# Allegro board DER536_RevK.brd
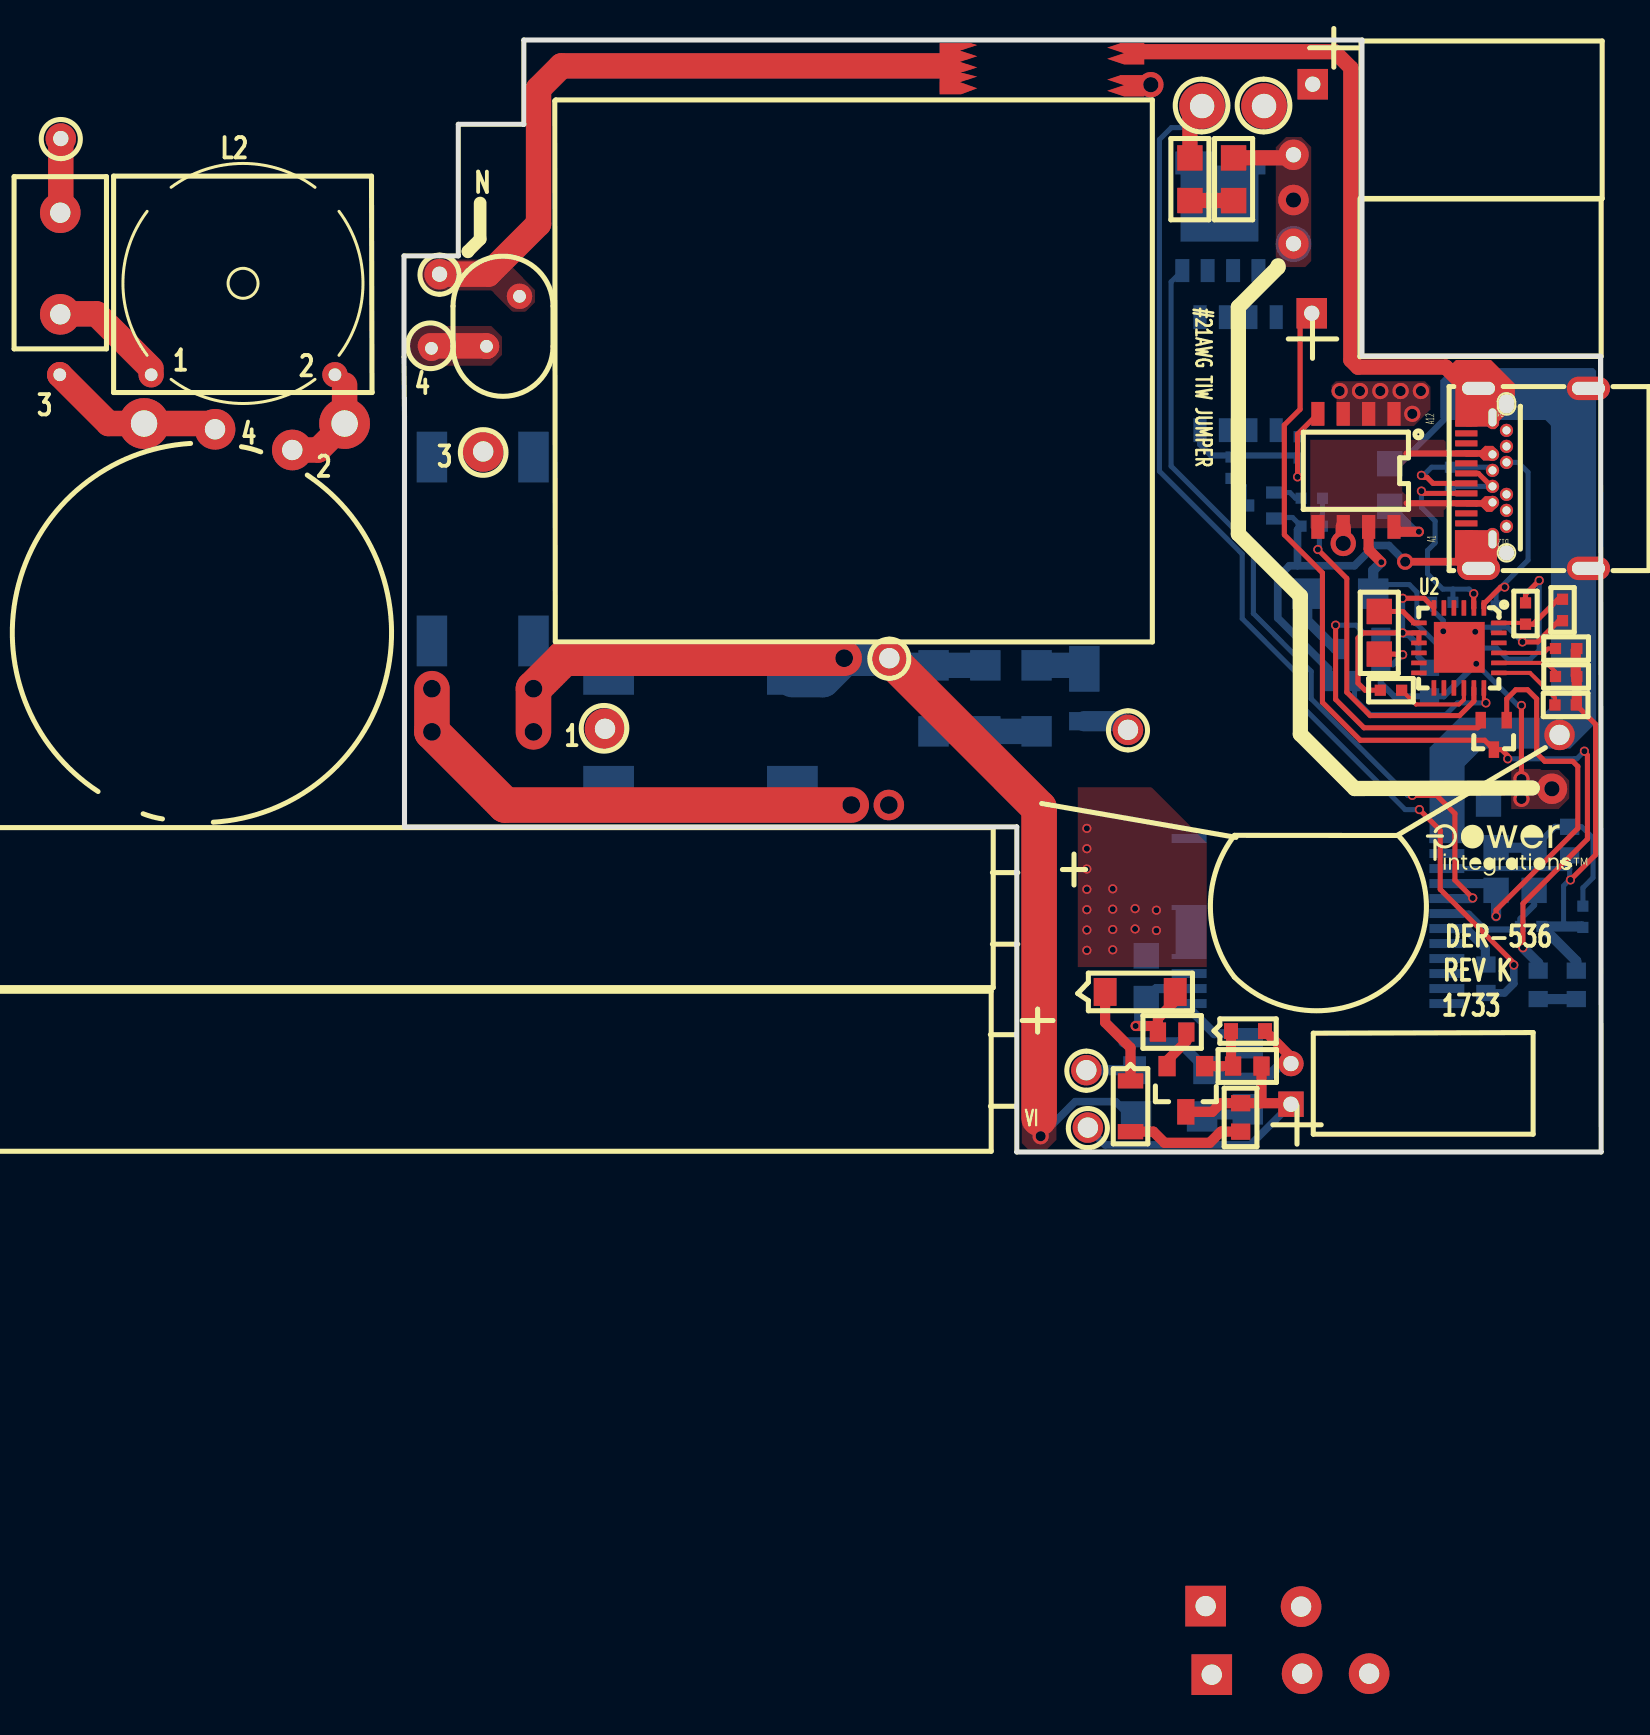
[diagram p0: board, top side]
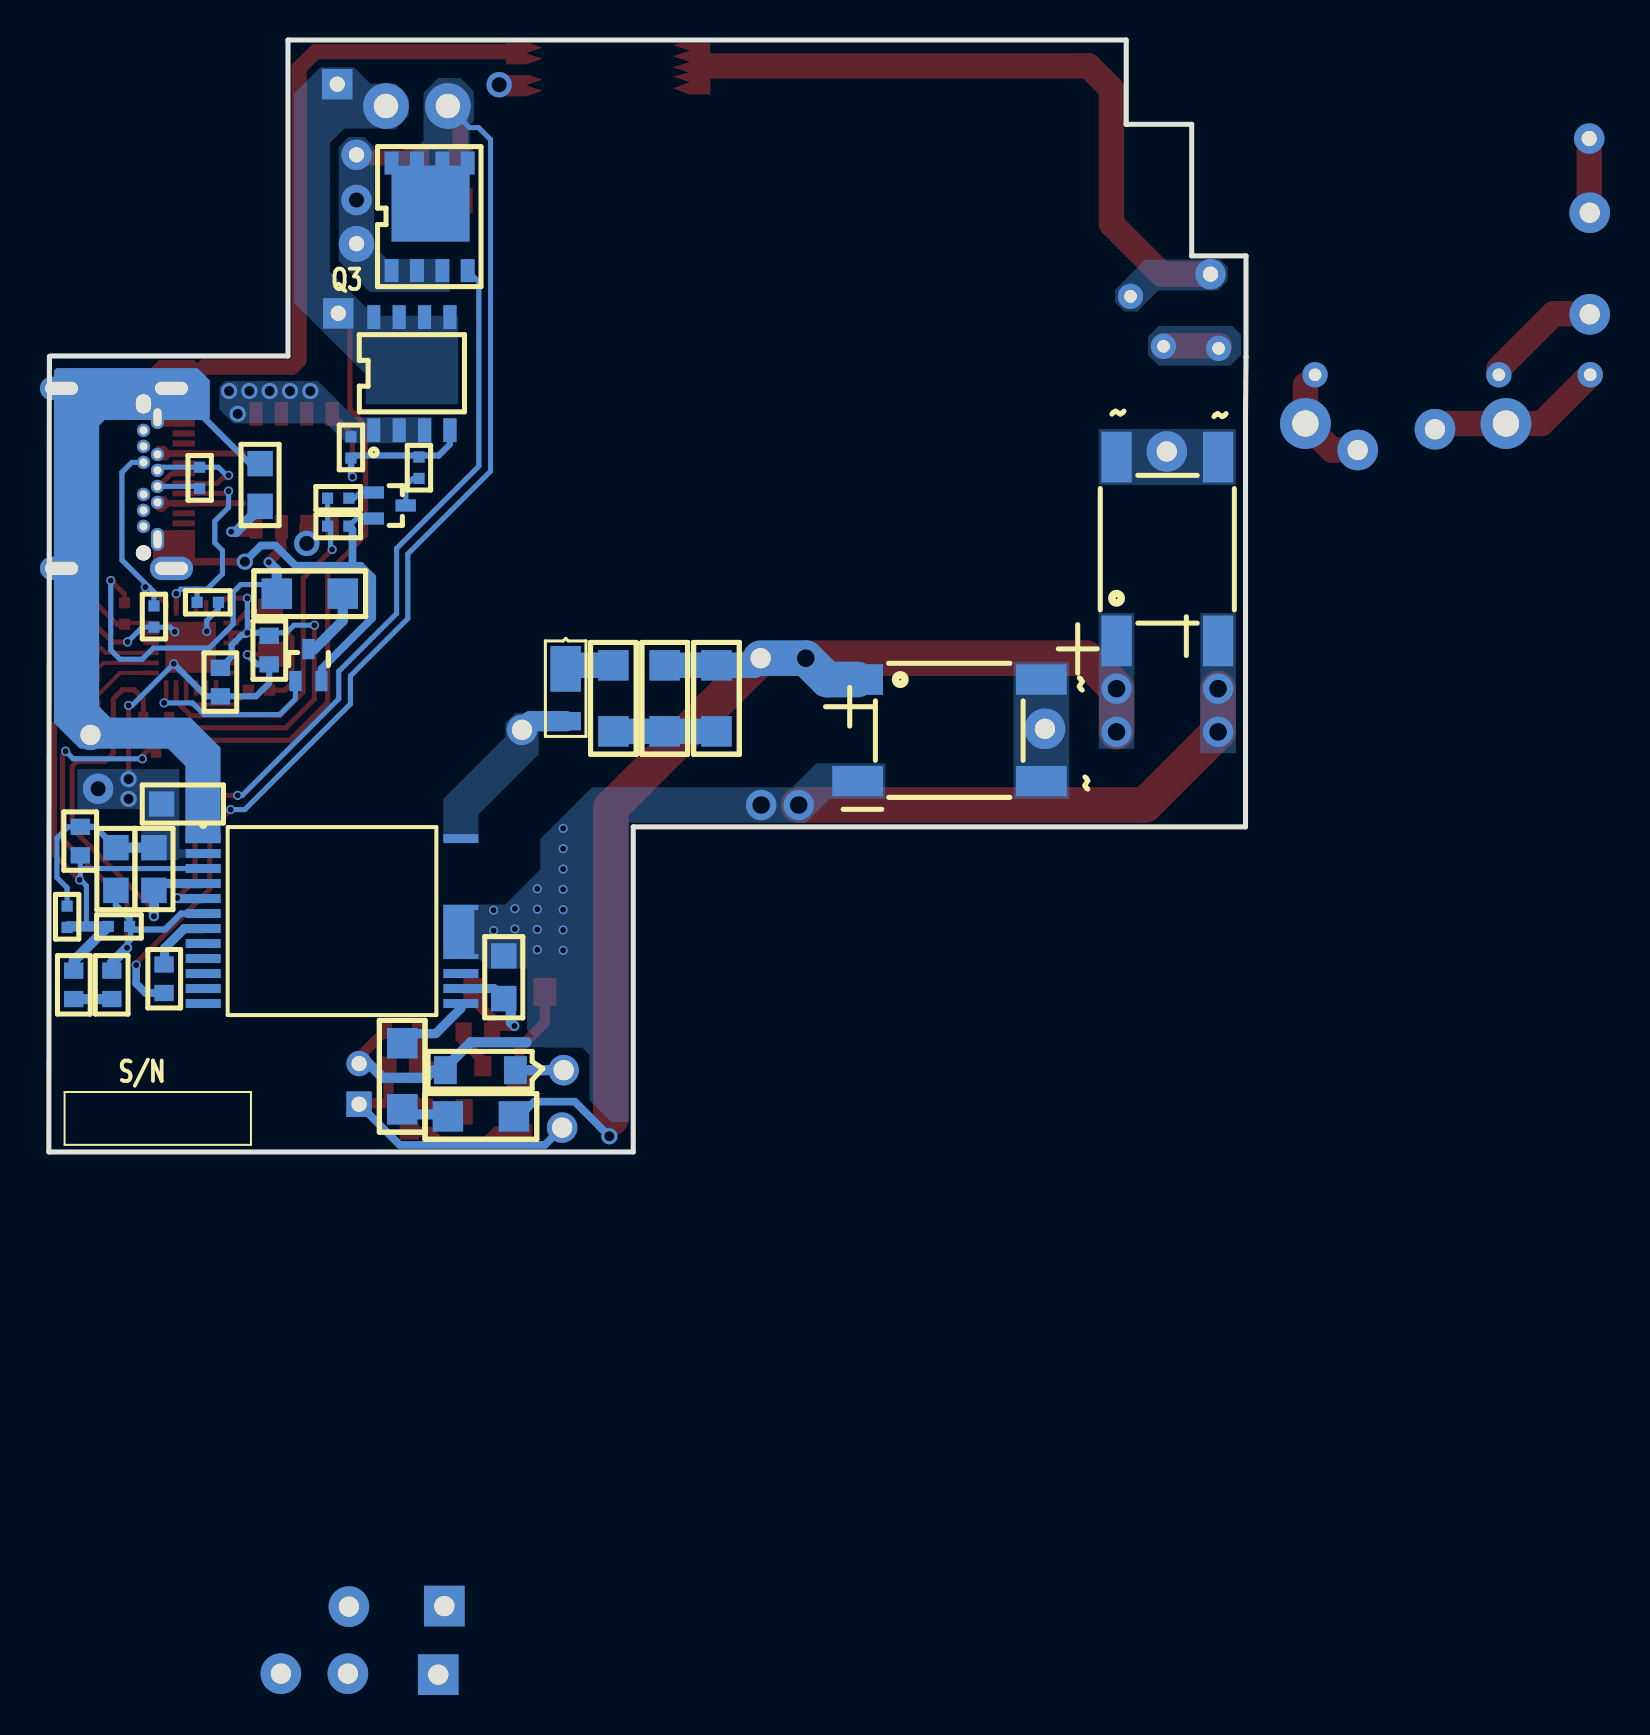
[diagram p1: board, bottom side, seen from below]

Outline 59.89 x 55.6 mm; copper layers: TOP, BOTTOM. Coordinates in mm from the lower left corner of the outline.
Outline path: 59.82,39.8 47.93,39.8 47.93,55.6 5.99,55.6 5.99,51.38 2.72,51.38 2.72,44.81 0,44.81 0,39.75 0.03,36.78 0.03,16.26 30.66,16.26 30.66,0 59.89,0 59.87,39.78

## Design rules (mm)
constraint set DEFAULT: min track width 0.508

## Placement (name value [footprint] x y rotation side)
BR1  TBS20J-TP  [PISMD_4-TBS]  6.48 25.6 0 bottom
BR2  TBS20J-TP  [PISMD_4-TBS]  19.38 23.62 90 bottom
C1  1 nF  [PINPYCAPRAD540X290LS400040H]  50.6 19.84 180 top
C2  39 uF  [PI_POLCAP315LS138D063]  31.98 13.97 270 top
C3  39 uF  [PI_POLCAP315LS138D063#2]  31.88 2.29 90 bottom
C4  2.2 nF  [PISMC1206]  29.08 24.33 270 bottom
C5  6.8 nF  [PISMC0603]  56.74 9.07 270 bottom
C6  390 uF  [PIPOLCAPCLYD320LS140030#2]  45.42 43.71 90 bottom
C7  390 uF  [PIPOLCAPCLYD320LS140030]  45.47 51.61 270 top
C8  1 nF  [PISMC0805]  41.5 47.57 90 top
C9  10 uF  [PISMC0805]  49.33 32.28 90 bottom
C10  2.2 uF  [PISMC0805]  54.64 15.21 270 bottom
C11  330 pF  [PISMC0603]  58.32 16.26 270 bottom
C12  100 nF  [PI_NP_XCAP_RAD512X197X395D040_H]  -2.97 36.42 180 top
C13  2.2 uF  [PISMC0805]  56.54 15.21 270 bottom
C14  22 uF  [PIPOLCAPCLYD200LS80030H]  44.37 2.39 90 top
C15  4.7 uF  [PISMC0805]  37.13 7.67 90 bottom
C16  100 nF  [PISMC0603]  51.31 24.21 270 bottom
C17  1 uF  [PISMC0603]  48.87 24.38 90 bottom
C18  1 uF  [PISMC0805]  48.79 24.89 90 top
C19  330 pF  [PISMR0402]  52.48 27.48 180 bottom
C20  330 pF  [PISMR0402]  54.64 27.3 270 bottom
D1  DFLR1800-7  [PISMDDFLR120012]  34.04 24.18 90 bottom
D2  BAV21WS-7-F  [PISMSOD323]  36.35 3.56 270 top
D3  SM4003PL-TP  [PI_SM_SOD-123_12]  36.55 4.09 0 bottom
F1  2 A  [PI_RST_MICROFUSE]  -17.2 46.96 270 top
FL1  Hole_30mils  [PI_HOLE_30MIL]  24.28 24.69 0 top
FL2  Hole_50mils  [PI_HOLE_50MIL]  39.93 52.3 0 top
FL3  Hole_50mils  [PI_HOLE_50MIL]  43.03 52.3 0 top
FL4  Hole_30mils  [PI_HOLE_30MIL]  36.22 21.11 0 top
FL5  Hole_30mils  [PI_HOLE_30MIL]  34.21 1.22 0 top
FL6  Hole_30mils  [PI_HOLE_30MIL]  34.14 4.09 0 top
J1  PCB Terminal 30 AWG  [PI_HOLE_30AWG]  -17.17 50.67 0 top
J2  PCB Terminal 30 AWG  [PI_HOLE_30AWG]  1.78 43.89 0 top
J3  USB-C/3.1  [PI_CONN_USB_3P1_TOP]  54.46 33.68 90 top
L1  34 mH  [PI_CMCHOKE_19X10MMH]  -10.77 15.78 165 top
L2  600 uH  [PI_TOROID_CMC4P_H]  -8.05 43.43 180 top
NOREF  -  []  0 44.81 0 top
NOREF#2  -  []  59.89 0 90 top
NOREF#3  -  []  -20.62 0.04 0 top
NOREF#4  -  []  50.57 16.28 0 top
NOREF#5  -  []  -174.86 61.37 0 top
NOREF#6  -  []  -252.68 -137.64 0 top
Q1  BSC030P03NS3 G  [PI_SM_PG-TDSON-8]  43.64 36.09 180 bottom
Q2  BSC030P03NS3 G  [PI_SM_PG-TDSON-8]  49.53 36.91 180 top
Q3  SIR882ADP-T1-GE3  [PI_SM_POWERPAK_SO-8_SINGLE]  42.75 44.07 180 bottom
Q4  RJU003N03T106  [PISMSOT323]  43.64 31.67 270 bottom
Q5  RJU003N03T106  [PISMSOT323]  46.25 23.55 180 bottom
Q6  RU1J002YNTCL  [PI_SM_UMT3F]  55.17 21.59 180 top
Q7  MMBTA06LT1G  [PISMSOT23123_1]  38.18 4.29 180 top
R1  2.00 M  [PISMR1206]  39.93 1.78 180 bottom
R2  150 k  [PISMR1206]  26.49 24.33 270 bottom
R3  1.80 M  [PISMR1206]  42.21 5.44 270 bottom
R4  100.0 k  [PISMR0402]  55.85 11.28 0 bottom
R5  20  [PISMR1206]  31.65 21.03 90 bottom
R6  49.9 k  [PISMR0402]  44.78 35.76 270 bottom
R7  200  [PISMR1206]  48.49 27.91 180 bottom
R8  10  [PISMR0805]  39.32 47.57 90 top
R9  1.00 k  [PISMR0402]  41.38 34.75 270 bottom
R10  4.02 k  [PISMR0603]  58.65 7.65 90 bottom
R11  10  [PISMR0402]  45.95 32.69 180 bottom
R12  100.0 k  [PISMR0402]  45.95 31.29 180 bottom
R13  47  [PISMR0603]  54.13 7.95 90 bottom
R14  402  [PISMR0603]  41.86 2.44 270 top
R15  1.50 M  [PISMR0603]  42.9 4.29 180 top
R16  31.6 k  [PISMR0402]  58.98 12.29 270 bottom
R17  31.6 k  [PISMR0402]  58.65 22.35 180 top
R18  18.0 k  [PISMR0402]  58.67 23.77 180 top
R19  12.7 k  [PISMR0402]  58.67 25.17 180 top
R20  4.02 k  [PISMR0603]  39.14 5.99 180 top
R21  0.01  [PISMR0805]  54.25 17.4 180 bottom
R22  100  [PISMR0402]  52.35 33.17 90 bottom
R23  100.0 k  [PISMR0402]  56.11 27.46 270 top
R24  10.0 k  [PISMR0402]  57.96 27.64 270 top
R25  4.7 k  [PISMR0402]  49.91 23.09 180 top
RT1  5  [PI_RAD_276DX197T_LS100D025]  4.95 40.28 90 top
U1  INN3268C  [PI_IC_INSOP_24D]  52.17 15.67 180 bottom
U2  CYPD2134-24LQXIT  [PI_SM_24_QFN]  54.03 27.2 180 top
VR1  MMSZ5259BT1G  [PI_SM_SOD-123_12]  35.08 8 0 top
VR2  DZ2S100M0L  [PI_SM_D_SSMINI2P]  41.38 6.05 0 top

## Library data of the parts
BR1 BR2 = DIODE BRIDGE_+-~~
C1 = CAP NP: alternate symbols: (pinpycaprad540x290ls400040h,pinpycaprad500x220ls400040)
C2 C3 = CAP POL: alternate symbols: (PI_POLCAP315LS138D063L2000H)
C4 C5 C8-C11 C13 C15-C20 = CAP NP
C6 C7 = CAP POL: alternate symbols: (pipolcapclyd320ls140d30h470)
C12 = CAP NP: alternate symbols: (pi_np_xcap_rad512x197x395d040_h)
C14 = CAP POL: alternate symbols: (pipolcapclyd200ls80030h)
D1-D3 = DIODE
F1 = FUSE: alternate symbols: (pirstmicrofusehoz)
FL1-FL6 = FlyingLead
J1 J2 = TERM_1Pin
J3 = CON24_USB: alternate symbols: (pi_conn_usb_3p1_topD)
L1 = TORRID 4P_12_34: alternate symbols: (pi_CMChoke_19x10mmH)
L2 = TORRID 4P_12_34: alternate symbols: (pi_toroid_CMC4p_V)
Q1 = FET_P_TDSON-8_15
Q2 = FET_P_TDSON-8_16
Q3 = FET_N_SGD_123_4_5678
Q4 Q5 = FET_N_SGD
Q6 = FET_N_GSD
Q7 = NPN_BEC
R1-R25 = R
RT1 = THERMISTOR
U1 = DEV_Inno3CP
U2 = CYPD2134-24LQXIT
VR1 VR2 = DIODE_ZENER

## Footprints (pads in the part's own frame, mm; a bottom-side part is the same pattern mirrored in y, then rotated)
PI_CMCHOKE_19X10MMH
  round 2.032 hole 1.016: 1(-18.723,-10.583) 2(0,-20) 3(-9.245,-22.401) 4(4,-20)
PI_CONN_USB_3P1_TOP
  oval 1.168x2.159 hole 0.66x1.651: (-4.5,0.7) (-4.5,-4.8) (4.5,0.7) (4.5,-4.8)
  round 0.762 hole 0.762: (-3.725,-0.7)
  oval 0.965x0.762 hole 0.965x0.762 unplated: (3.725,-0.7)
  rect 0.305x1.118 smd: A1(-2.75,1.31) A2(-2.25,1.31) A3(-1.75,1.31) A4(-1.25,1.31) A5(-0.75,1.31) A6(-0.25,1.31) A7(0.25,1.31) A8(0.75,1.31) A9(1.25,1.31) A10(1.75,1.31) A11(2.25,1.31) A12(2.75,1.31)
  oval 1.15x0.66 hole 0.9x0.406: B1(3.05,0) B12(-3.05,0)
  round 0.66 hole 0.406: B2(2.4,-0.7) B3(1.6,-0.7) B4(1.2,0) B5(0.8,-0.7) B6(0.4,0) B7(-0.4,0) B8(-0.8,-0.7) B9(-1.2,0) B10(-1.6,-0.7) B11(-2.4,-0.7)
PI_HOLE_30AWG
  round 1.524 hole 0.762: 1(0,0)
PI_HOLE_30MIL
  round 1.524 hole 1.016: 1(0,0)
PI_HOLE_50MIL
  round 2.286 hole 1.219: 1(0,0)
PI_IC_INSOP_24D
  rect 1.75x0.45 smd: 1(0,0) 2(0,-0.75) 3(0,-1.5) 4(0,-2.25) 5(0,-3) 6(0,-3.75) 7(0,-4.5) 8(0,-5.25) 9(0,-6) 10(0,-6.75) 11(0,-7.5) 12(0,-8.25) 13(12.89,-8.25) 14(12.89,-7.5) 15(12.89,-6.75) 24(12.89,0)
  custom 0.438x0.438 smd: 16(12.89,-4.67)
PI_NP_XCAP_RAD512X197X395D040_H
  round 2.54 hole 1.321: 1(0,0) 2(10.033,0)
PI_POLCAP315LS138D063
  rect 2.032x2.032 hole 1.016: 1(36.678,8.128)
  round 2.032 hole 1.016: 2(40.056,12.954)
PI_POLCAP315LS138D063#2
  rect 2.032x2.032 hole 1.016: 1(-28.423,8.534)
  round 2.032 hole 1.016: 2(-25.019,13.005)
PI_RAD_276DX197T_LS100D025
  round 1.27 hole 0.635: 1(0,0.826) 2(2.499,-0.826)
PI_RST_MICROFUSE
  round 2.032 hole 1.016: 1(0,0) 2(5.08,0)
PI_SM_24_QFN
  rect 0.231x0.775 smd: 1(0,0) 2(0.5,0) 3(1,0) 4(1.5,0) 5(2,0) 6(2.5,0) 13(2.5,4) 14(2,4) 15(1.5,4) 16(1,4) 17(0.5,4) 18(0,4)
  rect 0.775x0.231 smd: 7(3.25,0.75) 8(3.25,1.25) 9(3.25,1.75) 10(3.25,2.25) 11(3.25,2.75) 12(3.25,3.25) 19(-0.75,3.25) 20(-0.75,2.75) 21(-0.75,2.25) 22(-0.75,1.75) 23(-0.75,1.25) 24(-0.75,0.75)
  rect 2.54x2.54 smd: 25(1.23,1.97)
PI_SM_D_SSMINI2P
  rect 0.699x0.8 smd: 1(0,0) 2(1.699,0)
PI_SM_PG-TDSON-8
  rect 0.66x1.194 smd: 1(0,0) 2(1.27,0) 3(2.54,0) 4(3.81,0) 5(3.81,5.65) 6(2.54,5.65) 7(1.27,5.65) 8(0,5.65)
PI_SM_POWERPAK_SO-8_SINGLE
  rect 0.7x1.15 smd: 1(0,0) 2(1.27,0) 3(2.54,0) 4(3.81,0) 5(3.81,5.383) 6(2.54,5.383) 7(1.27,5.383) 8(0,5.383)
PI_SM_SOD-123_12
  rect 1.143x1.397 smd: 1(0,0) 2(3.505,0)
PI_SM_UMT3F
  rect 0.521x0.831 smd: 1(0,0) 2(1.301,0) 3(0.64,1.471)
PI_TOROID_CMC4P_H
  round 1.27 hole 0.635: 1(4.597,4.572) 2(-4.597,4.572) 3(9.169,4.572) 4(-9.423,3.251)
PINPYCAPRAD540X290LS400040H
  round 2.032 hole 1.016: 1(2.275,45.925)
  round 1.524 hole 1.016: 2(-7.213,-1.022)
PIPOLCAPCLYD200LS80030H
  rect 1.27x1.27 hole 0.762: 1(0,0)
  round 1.27 hole 0.762: 2(2.032,0)
PIPOLCAPCLYD320LS140030
  rect 1.524x1.524 hole 0.762: 1(-1.778,0)
  round 1.524 hole 0.762: 2(1.753,-0.965)
PIPOLCAPCLYD320LS140030#2
  rect 1.524x1.524 hole 0.762: 1(-1.778,0)
  round 1.524 hole 0.762: 2(1.702,-0.914)
PISMC0603
  rect 0.813x0.965 smd: 1(0,0) 2(1.422,0)
PISMC0805
  rect 1.27x1.27 smd: 1(0,0) 2(2.134,0)
PISMC1206
  rect 1.524x1.524 smd: 1(0,0) 2(3.302,0)
PISMD_4-TBS
  rect 1.524x2.54 smd: 1(0,0.051) 2(-5.08,0.051) 3(0,-9.144) 4(-5.08,-9.144)
PISMDDFLR120012
  rect 2.286x1.524 smd: 1(-0.025,0)
  rect 0.914x1.524 smd: 2(-2.642,0)
PISMR0402
  rect 0.559x0.559 smd: 1(0,0) 2(1.067,0)
PISMR0603
  rect 0.813x0.965 smd: 1(0,0) 2(1.422,0)
PISMR0805
  rect 1.27x1.27 smd: 1(0,0) 2(2.134,0)
PISMR1206
  rect 1.524x1.524 smd: 1(0,0) 2(3.302,0)
PISMSOD323
  rect 0.762x1.27 smd: 1(0,0) 2(2.54,0)
PISMSOT323
  rect 0.61x1.016 smd: 1(0,0) 2(-1.301,0) 3(-0.65,1.6)
PISMSOT23123_1
  rect 0.864x1.016 smd: 1(-1.88,0) 2(0,0)
  rect 0.864x1.27 smd: 3(-0.94,2.286)

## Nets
GND: C6.2 C7.2 C8.2 C10.1 C11.1 C13.1 C16.2 C17.1 C18.1 C19.2 C20.2 Q3.1(S) Q3.2 Q3.3 R16.1 R21.1 R24.2 U1.2 U2.25
VBUS_IN: C5.1 C6.1 C7.1 C13.2 FL3.1 Q1.5 Q1.6 Q1.7 Q1.8 Q6.3 R4.1 U1.6
VBUS_OUT: C9.1 J3.A4 J3.A9 J3.B4 J3.B9(VBUS4) Q2.5 Q2.6 Q2.7 Q2.8 R7.1 R23.1
VDD_SUPPLY: C16.1 C17.2 Q6.2(S) R25.2 U2.6 U2.8 U2.9
CCG2_CC1: C19.1 J3.A5 U2.2
CCG2_CC2: C20.1 J3.B5 U2.1
CCG2_VBUS_DISCHARGE: Q5.2 U2.18
CCG2_VBUS_P_CTRL: R11.1 R12.1 U2.17
D: FL2.1 Q3.5 Q3.6 Q3.7 Q3.8 R8.2 R13.1
D+: J3.A6 J3.B6 R22.2
D-: J3.A7 J3.B7 R22.1
NC8: U1.8
NC9: U1.9
NC10: U1.10
NC11: U1.11
NC12: U1.12
NC15: U1.15
RETURN: C1.2 C9.2 J3.A1 J3.A12 J3.B1 J3.B12 Q4.1(S) Q5.1(S) R12.2 R21.2 U1.1
S2: Q1.1(S1) Q1.2 Q1.3 Q2.1(S1) Q2.2 Q2.3 R6.1
V-PIN: R3.1 U1.13(VPIN)
VSEL_9V: R17.2 U2.19
VSEL_12V: R18.2 U2.20
VSEL_15V: R19.2 U2.21
N9603673: BR1.1 BR2.1 C1.1 C2.1 C3.1 C4.1 FL1.1 R1.2 R2.1
N10010568: BR1.2 BR2.2 C2.2 C3.2 C14.2 C15.2 D3.2 U1.16 VR2.2
N10479111: F1.1 J1.1
N10806149: C15.1 R20.2 U1.14 VR1.2
N10809540: Q3.4 U1.5
N10810926: C11.2 R4.2 R10.2 R16.2 R17.1 R18.1 R19.1 U1.3
N10813018: R1.1 R3.2
N10869805: C10.2 Q6.1 U1.4
N10873526: R13.2 U1.7
N10908947: BR2.3 BR2.4 L1.1
N10950053: C14.1 FL5.1 Q7.3 R14.1 R15.1
N10950141: Q7.2(EMITTER) R20.1
N10950189: Q7.1 R15.2 VR2.1
N10955093: C12.1 L1.2 L2.2
N10964883: C8.1 R8.1
N10966650: D1.2 FL4.1 U1.24
N10967740: C4.2 R2.2 R5.1
N11001432: Q1.4 Q2.4 R6.2 R9.1
N11001460: Q4.2 R11.2
N11001464: Q5.3 R7.2
N11001472: Q4.3 R9.2
N11008304: R23.2 R24.1 U2.24
N11008330: C18.2 U2.7
N11008640: R25.1 U2.16(XRES)
N11015378: C12.2 L1.4 L2.3
N11036082: D1.1 R5.2
N11061897: D3.1 FL6.1
N11077431: D2.2 R14.2
N11077448: D2.1 VR1.1
N11084818: BR1.3 BR1.4 L1.3
N11096040: C5.2 R10.1
N11100718: J2.1 RT1.2
N11100857: F1.2 L2.1
N11100955: L2.4 RT1.1

Pads without a net: J3 A2 A3 A8 A10 A11 B2 B3 B8 B10 B11; U2 3 4 5 10 11 12 13 14 15 22 23

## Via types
v1: diameter 1.27, hole 0.762, TOP to BOTTOM, 2 vias
v2: diameter 0.457, hole 0.305, TOP to BOTTOM, 44 vias
v3: diameter 0.813, hole 0.508, TOP to BOTTOM, 10 vias
v4: diameter 1.524, hole 0.889, TOP to BOTTOM, 7 vias
v5: diameter 1.524, hole 0.762, TOP to BOTTOM, 2 vias

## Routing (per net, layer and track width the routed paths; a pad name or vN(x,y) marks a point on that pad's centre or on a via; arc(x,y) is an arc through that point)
GND: length 35.1
  TOP w0.254: R24.2 57.79,26.57 56.72,25.5 v2(55.96,25.5) ; v2(49.96,24.87) 49.94,24.87 49.91,24.89 C18.1 ; v2(55.91,22.33) v3(55.91,18.64)
  TOP w0.762: C8.2 44.35,49.71 C7.2
  BOTTOM w0.254: v2(53.64,24.41) 55.73,22.33 v2(55.91,22.33) ; v2(53.59,26.01) 53.82,26.24 C20.2 55.22,26.24 v2(55.96,25.5) ; C19.2 51.41,27.15 51.99,26.57 v2(51.99,26.04) ; R16.1 58.98,13.21 59.49,13.72 59.49,15.7 58.93,16.26 C11.1
  BOTTOM w0.305: v2(53.64,24.41) 52.02,22.78 C16.2 49.53,22.78 48.87,23.44 C17.1 49.48,24.38 v2(49.96,24.87) ; C13.1 57.58,16.26 C11.1
  BOTTOM w0.508: C10.1 C13.1
  BOTTOM w1.778: C6.2 44.5,45.39
  vias: v3(55.91,17.65) v5(44.5,47.6) v5(57.43,18.16)
VBUS_IN: length 55.5
  TOP w0.254: v2(55.98,10.21) 55.98,12.42 59.21,15.65 59.21,19.84 59.05,19.99 v2(59.05,20.04) ; v2(55.22,19.66) 55.22,19.81 54.91,20.12 Q6.3 54.06,20.59 47.84,20.59 45.95,22.48 45.95,28.96 44.04,30.86 44.04,36.35 44.83,37.13 44.83,41.35 C6.1
  BOTTOM w0.254: v2(59.05,20.04) 58.68,19.66 58.58,19.66 58.57,19.66 v2(55.22,19.66) ; 55.83,11.2 55.83,11.25 ; 56.62,13.08 C13.2 ; 56.03,10.26 v2(55.98,10.21) 55.98,10.41 55.8,10.59 55.8,11.22
  BOTTOM w0.305: C13.2 56.54,12.34 55.85,11.66 R4.1 55.7,11.13 54.08,11.13 53.28,11.92 U1.6
  BOTTOM w0.508: C5.1 56.74,9.45 v2(55.98,10.21)
VBUS_OUT: length 35.2
  TOP w0.254: R23.1 56.11,27.89 v2(56.79,28.57)
  TOP w0.305: 53.65,32.44 50.17,32.44 ; 53.65,32.44 54.41,32.44 ; 53.65,32.44 53.65,32.43 ; 54.41,32.44 J3.B9 ; 54.41,32.44 54.41,32.43 53.65,32.43 ; J3.A9 54.41,34.93 54.41,34.93 ; 50.15,34.93 54.41,34.93 ; 54.41,34.93 J3.B4 ; 53.65,32.43 J3.A4
  TOP w0.508: Q2.8 49.77,31.01 v2(50.77,31.01) ; v2(48.9,29.49) 48.29,30.1 48.29,30.13 48.26,30.15 Q2.7
  TOP w0.762: Q2.6 v1(46.99,30.43)
  BOTTOM w0.254: v2(56.79,28.57) 56.79,25.1 56.34,24.64 55.22,24.64 54.66,25.2 51.87,25.2 50.67,26.39 50.67,27.99 50.29,28.37 49.23,28.37 48.77,27.91 R7.1
  BOTTOM w0.508: v2(48.9,29.49) 48.49,29.08 R7.1 ; C9.1 49.33,32.21 50.52,31.01 v2(50.77,31.01)
VDD_SUPPLY: length 28.7
  TOP w0.254: U2.9 U2.8 49.97,25.95 v2(49.96,25.96) 49.89,25.96 49.88,25.95 47.98,25.95 47.73,25.7 47.73,23.44 48.08,23.09 R25.2 ; v2(46.61,26.34) 46.61,22.63 48.03,21.21 53.72,21.21 53.87,21.36 Q6.2 ; 49.96,27.72 v2(49.96,27.69) 51.04,27.69 U2.6
  BOTTOM w0.254: 49.02,25.96 48.01,25.96 47.62,26.34 v2(46.61,26.34) ; v2(49.96,27.69) v2(49.96,25.96)
  BOTTOM w0.305: C16.1 50.75,24.77 50.75,25.35 50.24,25.86 50.06,25.86 v2(49.96,25.96) 49.02,25.96 48.97,26.01 ; 48.79,25.96 48.87,25.88 C17.2
CCG2_CC1: length 11
  TOP w0.254: J3.A5 51.02,32.93 v2(50.9,33.05) ; U2.2 53.52,27.21 v2(53.52,27.91)
  BOTTOM w0.254: v2(53.52,27.91) 53.29,28.14 52.48,28.14 ; 52.48,28.14 C19.1 ; 52.48,28.14 51.97,28.14 51.21,28.91 51.21,30.07 51.59,30.45 51.59,31.55 50.9,32.23 v2(50.9,33.05)
CCG2_CC2: length 10.8
  TOP w0.254: U2.1 54.03,27.41 54.86,28.24 v2(55.07,28.24)
  BOTTOM w0.254: 54.71,27.3 C20.1 54.64,27.99 ; J3.B5 55.74,34.48 56.24,33.99 56.24,29.6 54.64,28 54.64,27.99 ; 54.64,27.99 54.89,28.24 v2(55.07,28.24)
CCG2_VBUS_DISCHARGE: length 8.8
  TOP w0.203: v2(54.13,22.45) 54.03,22.56 U2.18
  BOTTOM w0.254: Q5.2 47.55,22.66 48.34,21.87 52.12,21.87 52.71,22.45 v2(54.13,22.45)
CCG2_VBUS_P_CTRL: length 18.2
  TOP w0.254: U2.17 53.53,22.54 52.81,21.82 48.34,21.82 47.17,22.99 47.17,28.68 v2(45.72,30.12)
  BOTTOM w0.254: R11.1 R12.1 45.8,31.14 45.8,30.2 v2(45.72,30.12)
D: length 57.2
  TOP w0.254: v2(55.52,9.35) 55.52,9.45 51.84,13.13 51.84,16.08 v2(50.8,17.12)
  TOP w0.762: FL2.1 39.32,51.69 R8.2
  BOTTOM w0.254: v2(50.8,17.12) 50.09,17.12 44.81,22.4 44.81,23.8 41.94,26.67 41.94,29.9 37.8,34.04 37.8,50.62 38.39,51.22 38.85,51.22 FL2.1
  BOTTOM w0.381: R13.1 55.05,7.95 55.52,8.42 v2(55.52,9.35)
D+: length 6.2
  TOP w0.254: J3.A6 51.48,33.43 51.18,33.73 51,33.73 v2(50.9,33.83)
  BOTTOM w0.254: J3.B6 54.3,34.24 R22.2 51.41,34.24 51,33.83 v2(50.9,33.83)
D-: length 3.7
  TOP w0.254: J3.B7 54.4,33.28 53.75,33.93 J3.A7
  BOTTOM w0.254: J3.B7 52.46,33.28 R22.1
RETURN: length 62.2
  TOP w0.305: J3.B1 53.7,36.73 53.4,36.43 J3.A12 ; J3.B12 53.7,30.63 53.4,30.93 J3.A1
  TOP w0.381: v3(50.09,29.51) 53.59,29.51 54.46,30.39 J3.B12
  TOP w0.762: 52.88,38.48 52.12,39.24 47.73,39.24 47.37,39.6 47.37,54.2 46.56,55.02 36.63,55.02
  BOTTOM w0.254: Q4.1 43.69,31.72 44.45,31.72 R12.2
  BOTTOM w0.305: C9.2 49.83,34.42 52.98,37.57 52.98,38.1 52.88,38.2
  BOTTOM w0.381: 44.7,29.31 47.55,29.31 48.56,30.32 49.28,30.32 v3(50.09,29.51) ; 44.7,29.31 44.7,31.11 R12.2 ; 44.7,29.31 44.3,29.31 43.71,28.73 43.71,26.7 46.25,24.16 Q5.1
S2:
  vias: v3(46.81,38.05) v3(47.83,38.05) v3(48.84,38.05) v3(49.86,38.05) v3(50.44,36.91) v3(50.88,38.05)
V-PIN: length 3.9
  BOTTOM w0.457: U1.13 39.28,7.17 40.54,5.92 41.55,5.92 42.04,5.44 R3.1
VSEL_9V: length 3.7
  TOP w0.203: R17.2 57.58,22.71 56.34,23.95 U2.19
VSEL_12V: length 3.2
  TOP w0.203: R18.2 57.61,24 57.16,24.45 U2.20
VSEL_15V: length 2.9
  TOP w0.203: R19.2 57.25,25.17 57.03,24.95 U2.21
N9603673: length 60.5
  TOP w1.778: v4(6.48,21.01) v4(6.48,23.16) 8,24.69 v4(22.02,24.69) ; 31.78,1.68 31.78,17.2 FL1.1
  BOTTOM w0.381: v3(31.85,0.79) 33.58,2.51 35.61,2.51 36.35,1.78 R1.2
  BOTTOM w1.27: FL1.1 24.64,24.33 R2.1 C4.1
  BOTTOM w1.778: FL1.1 v4(22.02,24.69) 20.96,23.62 BR2.1
N10010568: length 36.4
  TOP w0.508: VR2.2 44.37,4.75 C14.2
  TOP w1.778: v4(22.38,17.35) 5.05,17.35 v4(1.4,21.01) v4(1.4,23.16)
  BOTTOM w0.508: C14.2 43.89,4.42 43.18,3.71 41.02,3.71 40.64,4.09 D3.2 40.06,4.22 38.79,5.49 35.99,5.49 ; 39.28,10.86 U1.16
  vias: v2(34.16,16.18) v2(34.16,15.16) v2(34.16,14.15) v2(34.16,13.13) v2(34.16,12.12) v2(34.16,11.1) v2(34.16,10.08) v2(35.46,13.16) v2(35.46,12.14) v2(35.46,11.13) v2(35.46,10.11) v2(36.58,12.17) v2(36.58,11.15) v2(37.64,12.09) v2(37.64,11.07) v4(24.26,17.35)
N10479111: length 3.7
  TOP w1.27: J1.1 -17.17,46.99 F1.1
N10806149: length 7.4
  TOP w0.508: 37.72,6.33 37.68,6.3 v2(36.6,6.3) ; 37.72,6.33 R20.2 ; 37.72,6.33 37.72,6.68 38.58,7.54 VR1.2
  BOTTOM w0.457: C15.1 37.64,8.17 U1.14
  BOTTOM w0.508: C15.1 36.78,7.32 36.78,6.48 v2(36.6,6.3)
N10809540: length 40
  TOP w0.254: v2(50.44,17.83) 51.66,17.83 52.58,16.92 52.58,13.59 v2(53.47,12.7)
  BOTTOM w0.254: Q3.4 38.38,43.51 38.38,34.29 42.49,30.18 42.49,26.92 45.39,24.03 45.39,22.66 50.22,17.83 v2(50.44,17.83)
  BOTTOM w0.457: v2(53.47,12.7) 53.44,12.67 U1.5
N10810926: length 28.6
  TOP w0.254: v2(58.36,13.6) 59.61,14.86 59.61,21.39 R17.1
  TOP w0.508: R17.1 58.67,22.38 R18.1 58.62,23.83 58.62,25.1 58.67,25.15 R19.1
  BOTTOM w0.254: C11.2 58.32,14.15 ; 58.32,14.15 58.29,14.17 U1.3 ; 58.32,14.15 58.32,13.64 v2(58.36,13.6) 58.31,13.6 58.01,13.31 58.01,11.35 57.91,11.25
  BOTTOM w0.305: R16.2 58.29,11.23 58.27,11.25 57.91,11.25
  BOTTOM w0.508: R10.2 58.65,9.55 R4.2 58.93,11.28 R16.2
N10813018: length 2.4
  BOTTOM w0.508: R1.1 40.03,1.88 41.96,1.88 R3.2
N10869805: length 21.2
  TOP w0.254: 55.17,21.51 Q6.1 55.17,22.66 55.63,23.11 56.21,23.11 56.67,22.66 56.67,19.94 57.07,19.53 58.47,19.53 58.72,19.28 58.72,16.18 54.64,12.09 v2(54.64,11.79)
  BOTTOM w0.457: U1.4 54.29,13.42
  BOTTOM w0.508: v2(54.64,11.79) C10.2 54.29,13.42
N10873526: length 3.2
  BOTTOM w0.457: R13.2 54.1,9.4 54.1,10.19 53.12,11.17 U1.7
N10950053: length 18.7
  TOP w0.508: C14.1 44.32,2.44 42.85,2.44 ; 42.85,2.44 42.9,2.49 R15.1 ; 42.85,2.44 R14.1 40.87,2.44 40.44,2.01 Q7.3
  BOTTOM w0.381: FL5.1 35.08,0.36 42.34,0.36 C14.1
N10950141: length 2.1
  TOP w0.508: R20.1 39.14,5.54 38.18,4.57 Q7.2
N10950189: length 3.2
  TOP w0.508: VR2.1 41.38,4.39 R15.2 Q7.1
N10955093: length 5.8
  TOP w0.508: L2.2 -2.97,38.35
  TOP w1.27: L1.2 -4.29,35.1 C12.1 -2.97,38.35
N10964883: length 2.2
  TOP w0.762: R8.1 C8.1
N10966650: length 2.4
  BOTTOM w1.016: D1.2 35.79,21.54 FL4.1
N10967740: length 5.2
  BOTTOM w1.27: R5.1 C4.2 R2.2
N11001432: length 10.6
  TOP w0.254: Q2.4 44.7,35.89 v2(44.7,33.76)
  BOTTOM w0.254: R9.1 41.3,34.82
  BOTTOM w0.305: v2(44.7,33.76) 44.78,33.83 R6.2 44.65,34.82 40.39,34.82 39.83,35.38 Q1.4
N11001460: length 1.4
  BOTTOM w0.254: R11.2 44.6,32.69 44.32,32.97 Q4.2
N11001464: length 3.7
  BOTTOM w0.508: R7.2 45.19,26.57 46.61,25.15 Q5.3
N11001472: length 1.8
  BOTTOM w0.254: R9.2 41.67,33.68 42.04,33.31 Q4.3
N11008304: length 3.7
  TOP w0.203: U2.24 55.92,26.45 55.98,26.39 R23.2
  TOP w0.254: R23.2 56.49,26.39 57.73,27.64 R24.1
N11008330: length 2.2
  TOP w0.254: U2.7 50.55,26.45 49.97,27.03 C18.2
N11008640: length 4.1
  TOP w0.203: R25.1 50.62,22.38 52.78,22.38 53.03,22.62 U2.16
N11015378: length 8.9
  TOP w1.27: L1.4 -9.74,36.42 C12.2 -14.78,36.42 L2.3
N11036082: length 2.5
  BOTTOM w1.27: D1.1 33.86,24.33 R5.2
N11061897: length 2.4
  BOTTOM w0.508: D3.1 FL6.1
N11077431: length 6
  TOP w0.508: R14.2 40.87,1.02 40.31,0.46 38.05,0.46 37.49,1.02 D2.2
N11077448: length 5
  TOP w0.508: D2.1 36.35,5.21 35.08,6.48 VR1.1
N11096040: length 1.9
  BOTTOM w0.508: C5.2 R10.1
N11100718: length 34.3
  TOP w0.762: 36.63,53.37 v1(37.36,53.37)
  TOP w1.27: 27.08,54.33 27.05,54.31 7.87,54.31 6.73,53.16 6.73,46.41 4.22,43.89 J2.1
N11100857: length 6
  TOP w0.508: L2.1 -12.65,39.17
  TOP w1.27: F1.2 -17.17,41.91 -15.39,41.91 -12.65,39.17
N11100955: length 2.8
  TOP w1.27: RT1.1 4.1,40.31 1.32,40.31

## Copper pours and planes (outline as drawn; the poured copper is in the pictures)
GND on TOP: 44.88,50.75 44.12,50.75 43.61,50.24 43.61,44.75 44.12,44.25 45.09,44.25 45.39,44.55 45.39,50.24
GND on TOP: 57.76,17.14 55.4,17.14 55.4,19.15 57.71,19.15 58.32,18.54 58.32,17.7
GND on BOTTOM: 53.37,19.15 58.47,19.15 58.47,17.14 55.27,17.14 55.27,14.58 53.47,14.58 53.34,14.71 51.28,14.71 51.28,15.14 53.04,15.14 53.37,15.47
GND on BOTTOM: 39.88,44.65 42.98,44.65 43.61,45.29 43.61,50.24 44.12,50.75 44.88,50.75 45.39,50.24 45.39,44.55 43.84,43 39.85,43 39.85,44.63
VBUS_IN on BOTTOM: 42.55,53.42 43.81,53.42 44.63,54.23 46.3,54.23 47.62,52.91 47.62,42.47 44.04,38.89 44.04,37.39 39.42,37.39 39.42,41.81 43.61,41.81 45.82,44.02 45.82,50.47 45.11,51.18 42.93,51.18 42.88,51.13 42.57,51.13 41.88,51.82 41.88,52.73
VBUS_OUT on TOP: 50.39,32.59 49.94,33.05 49.94,34.29 50.42,34.77 52.25,34.77 52.22,34.8 52.22,35.08 52.2,35.08 52.12,35.15 52.12,35.51 52.02,35.61 45.34,35.61 45.34,31.19 50.39,31.19 50.39,31.75 52.02,31.75 52.02,32.08 52.32,32.39 52.32,32.46 52.2,32.59
D on BOTTOM (solid shape): 42.75,45.52 38.85,45.52 38.85,49.32 42.75,49.32
D on BOTTOM: 41.68,50.04 42.75,50.04 42.75,45.52 38.86,45.52 38.84,45.54 38.84,51.33 38.62,51.55 38.62,52.64 38.63,52.65 38.63,53.04 39.29,53.7 40.41,53.7 41.15,52.96 41.15,50.57
RETURN on TOP (solid shape): 54.69,30.99 54.69,29.08 54.28,28.68 53.01,28.68 52.81,28.88 52.81,29.18 52.58,29.41 52.58,31.09 54.58,31.09
RETURN on TOP (solid shape): 55.58,38.4 55.58,37.11 55.35,36.88 55.12,36.88 54.76,36.53 54.76,36.32 54.58,36.14 54.38,36.14 54.25,36.27 52.6,36.27 52.6,38.71 52.37,38.94 52.37,39.34 52.63,39.6 54.38,39.6
RETURN on BOTTOM (solid shape): 59.64,39.07 59.64,21.46 58.34,20.17 53.92,20.17 53.06,19.3 53.06,15.44 51.31,15.44 51.31,20.22 52.81,21.72 56.82,21.72 57.38,22.28 57.38,36.32 57.1,36.6 51.94,36.6 51.84,36.7 51.84,38.58 52.45,39.19 59.51,39.19
S2 on TOP: 46.66,36.3 50.52,36.3 51.36,37.13 51.36,38.25 51.08,38.53 46.61,38.53 46.41,38.33 46.41,37.87 46.66,37.62
S2 on BOTTOM: 40.72,36.73 44.6,36.73 46.42,38.54 51.08,38.54 51.37,38.26 51.37,37.36 51.36,37.36 51.36,37.14 50.65,36.42 46,36.42 45.01,35.43 40.72,35.43
N9603673 on TOP: 32.64,1.6 32.64,0.61 32.18,0.15 31.19,0.15 30.91,0.43 30.91,1.78 30.99,1.85 32.39,1.85
N9603673 on BOTTOM: 5.59,26.95 7.37,26.95 7.37,20.17 5.59,20.17
N10010568 on TOP: 33.71,18.24 33.71,9.25 40.16,9.25 40.16,15.47 37.39,18.24
N10010568 on BOTTOM: 35.31,14.12 35.31,15.65 32.72,18.24 22.68,18.24 21.49,19.43 18.03,19.43 18.03,17.65 20.83,17.65 22.02,16.46 30.89,16.46 30.89,1.5 31.75,1.5 32.84,2.59 32.84,4.85 33.2,5.21 35.08,5.21 35.1,5.23 36.07,5.23 36.07,5.74 35.61,5.74 35.97,6.1 35.97,9.17 37.9,9.17 38.38,9.65 40.16,9.65 40.16,12.37 37.06,12.37
N10010568 on BOTTOM: 0.51,26.95 0.51,19.94 2.29,19.94 2.29,26.95
N10908947 on BOTTOM: 8.84,17.65 8.84,24.51 11.63,24.51 11.63,17.65
N10966650 on BOTTOM: 40.16,15.44 40.16,17.65 37.06,20.75 37.06,21.44 36.55,21.95 35.89,21.95 35.38,21.44 35.38,19.89 38.4,16.87 38.4,15.44
N11084818 on BOTTOM: 0.51,36.14 7.37,36.14 7.37,33.35 0.51,33.35
N11100718 on TOP (solid shape): 37.03,54.38 36.02,54.38 35.18,54.66 36.02,54.94 35.18,55.22 35.84,55.44 35.84,55.45 37.03,55.45
N11100718 on TOP (solid shape): 37.03,52.78 36.02,52.78 35.18,53.06 36.02,53.34 35.18,53.62 35.84,53.84 35.84,53.85 37.03,53.85
N11100718 on TOP (solid shape): 28.68,55.35 27.81,55.07 28.68,54.79 27.81,54.51 28.68,54.23 27.99,54.01 27.84,53.98 28.68,53.77 27.81,53.49 28.68,53.19 27.86,52.88 26.8,52.88 26.8,53.47 26.8,53.49 26.8,55.45 28.35,55.45
N11100718 on TOP: 6.55,43.1 6.55,42.49 6.07,42.01 5.44,42.01 4.37,43.08 1.37,43.08 1.02,43.43 1.02,43.46 0.94,43.54 0.91,43.54 0.91,44.25 1.3,44.63 5.03,44.63
N11100718 on BOTTOM: 1.3,44.63 5.03,44.63 6.55,43.1 6.55,42.49 6.08,42.02 5.44,42.02 4.38,43.08 1.4,43.08 0.91,43.56 0.91,44.25
N11100955 on TOP: 0.25,40.87 0.25,39.85 0.79,39.32 4.37,39.32 4.9,39.85 4.9,40.77 4.37,41.3 0.69,41.3
N11100955 on BOTTOM: 0.25,39.85 0.25,40.87 0.69,41.3 4.37,41.3 4.9,40.77 4.9,39.85 4.37,39.32 0.79,39.32

Small or netless copper shapes (teardrops, artwork), in the pictures only: 2 on TOP

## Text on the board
Ref Des/Silkscreen Bottom: S/N
Ref Des/Silkscreen Top: VI | #21AWG TIW JUMPER | N | 1733 | REV K | DER-536
BODY_CENTER: PLEASE DELETE THESE ITEMS: | 14. FAB HOUSE LOGO,DATE CODE TO BE IN SILK SCREEN ONLY.DO NOT USE COPPER. | CUT OUT | 2 SLOTS | PLEASE DELETE THESE PINS | 7 SLOTS | 13   MATERIAL FR4 COPPER 2oz THICKNESS 0.031"
User.5: FIGURE | FINISHED_SIZE | 12.0 | 16.0 | 20.0 | 25.0 | 30.0 | 35.0 | 40.0 | 48.0 | 52.0 | 35.433x16.0 | 65.0x26.0 | 38.0x30.0 | DRILL CHART: TOP to BOTTOM | ALL UNITS ARE IN MILS | ROTATION | - | 90.000 | 0.000 | PLATED | NON-PLATED | QTY | 44 | 10 | 6 | 13 | 7 | 16 | 2 | 4 | 1
